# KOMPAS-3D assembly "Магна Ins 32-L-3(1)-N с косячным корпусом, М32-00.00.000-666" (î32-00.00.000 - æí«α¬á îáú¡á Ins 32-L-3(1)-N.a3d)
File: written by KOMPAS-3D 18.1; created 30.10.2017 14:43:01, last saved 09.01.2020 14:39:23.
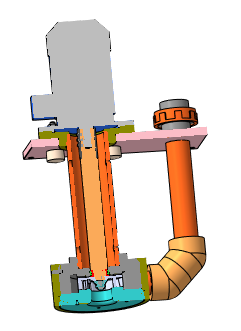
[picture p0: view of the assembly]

Document properties: Автор: Милов; Организация: Милов; Полное имя файла: D:\Magna\Магна Ins\Магна ins 32\Для Караби Магна 32\М32-00.00.000 - Сборка Магна Ins 32-L-3(1)-N.a3d

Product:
- Part/product: Магна Ins 32-L-3(1)-N с косячным корпусом  | designation М32-00.00.000-666
    Масса: 40.608
  - Component [detail]: Защитная втулка  | designation М11-00.00.003  | pos. 71  | Масса: 0.0186143; Раздел спецификации: Детали; Форматы листов документа: A4; source file: ..\..\Магна ins 11\Магна N\3Д\Магна INS 11\М11-00.00.003 - Защитная втулка.m3d, ..\..\Магна ins 11\Магна N\3Д\Магна INS 11\Чертежи\М11-00.00.003 - Защитная втулка.cdw
  - Component [detail]: Втулка / скольжения  | designation М11-00.00.002  | pos. 70  | Масса: 0.026501; Раздел спецификации: Детали; Форматы листов документа: A4
  - Component [detail]: Заглушка  | designation М32-00.00.007М32  | pos. 9  | Раздел спецификации: Детали; Форматы листов документа: A3; source file: ..\..\Магна ins 40\3Д\М40-00.00.007-01 - Заглушка.m3d, М32-00.00.007 - Заглушка.cdw
  - Component [detail]: Заглушка @2~32 FV PPR ф. "FV-Plast"  | qty 3  | pos. 19  | Материал: Полипропилен  ГОСТ 26996-86 (density 900 kg/m3); Масса: 0.0281994; Раздел спецификации: Прочие изделия
  - Component [detail]: Кольцо 120-125-30 EPDM / ГОСТ 9833-73  | pos. 18  | Раздел спецификации: Прочие изделия
  - Component [assembly]: Вал  | designation М32-00.10.000  | pos. 2  | Масса: 1.67698; Раздел спецификации: Сборочные единицы; Форматы листов документа: A3; Примечание: См. заказ
  - Component [assembly]: Корпус М32 с косячным корпусом М40  | designation М32-00.15.000-666  | pos. 1  | Масса: 9.75067; Раздел спецификации: Сборочные единицы; Форматы листов документа: A3; Примечание: См. заказ; source file: ..\М32-00.15.000 - Корпус М32.a3d
  - Component [detail]: Заглушка  | designation М32-00.00.007  | pos. 9  | Раздел спецификации: Детали; Форматы листов документа: A3
  - Component [detail]: Втулка  | designation М32-00.00.002  | pos. 7  | Раздел спецификации: Детали; Форматы листов документа: A4
  - Component [detail]: Защитная втулка  | designation М32-00.00.001  | pos. 6  | Раздел спецификации: Детали; Форматы листов документа: A4
  - Component [detail]: Косячная (удолить)  | designation М40-00.00.007-6666  | pos. 118  | Масса: 8.81523; Раздел спецификации: Детали; Форматы листов документа: 3xA3; Примечание: @100~)3xA3; source file: ..\..\Магна ins 40\3Д\М40-00.00.007-01 - Заглушка.m3d, ..\Магна ins 40\3Д\М40-00.00.007-06 - Заглушка.cdw
- Part/product: Сборка Магна Ins 32-L-3(1)-N  | designation М32-00.00.000
    Масса: 40.6372
    source file: М32-00.00.000 СБ - Магна Ins 32-L-3(1)-N.cdw
  - Component [standard]: Шайба C.14.21 ГОСТ 11371-78  | qty 7  | pos. 15
      Материал: Сталь 12Х18Н10Т ГОСТ 5632-72 (density 1000 kg/m3)
      Масса: 0.008377
      Раздел спецификации: Стандартные изделия
      Примечание: нерж.
      additional columns: Сталь 12Х18Н10Т ГОСТ 5632-72
      source file: C:\Program Files\ASCON\KOMPAS-3D v18\Libs\PartLib\DATA\VAULT\methods\kompas\3d\PLib_Washer_1_712.m3d
  - Component [detail]: Заглушка 32 FV PPR ф. "FV-Plast"  | qty 4  | pos. 19  | Материал: Полипропилен  ГОСТ 26996-86 (density 900 kg/m3); Масса: 0.0281994; Раздел спецификации: Прочие изделия; source file: Заглушка ф32 FV PPR ф. FV-Plast.m3d
  - Component [standard]: Шайба C.14.21 ГОСТ 11371-78  | qty 7  | pos. 15  | Материал: Сталь 12Х18Н10Т ГОСТ 5632-72 (density 1000 kg/m3); Масса: 0.008377; Раздел спецификации: Стандартные изделия; additional columns: Сталь 12Х18Н10Т ГОСТ 5632-72; source file: C:\Program Files\ASCON\KOMPAS-3D v18\Libs\PartLib\DATA\VAULT\methods\kompas\3d\PLib_Washer_1_712.m3d
  - Component [standard]: Шайба 14 30Х13 019 ГОСТ 6402-70  | qty 3  | pos. 120  | Материал: Сталь 30Х13 ГОСТ 5632-72 (density 1000 kg/m3); Масса: 0.00448; Раздел спецификации: Стандартные изделия; source file: C:\Program Files\ASCON\KOMPAS-3D v18\Libs\PartLib\DATA\VAULT\methods\kompas\3d\PLib_Washer_2_712.m3d
  - Component [standard]: Гайка М14-6H.21.12Х18Н10Т ГОСТ 5915-70  | qty 7  | pos. 13
      Материал: Сталь 12Х18Н10Т ГОСТ 5632-72 (density 1000 kg/m3)
      Масса: 0.02891
      Раздел спецификации: Стандартные изделия
      Примечание: нерж.
      additional columns: Сталь 12Х18Н10Т ГОСТ 5632-72
      source file: C:\Program Files\ASCON\KOMPAS-3D v18\Libs\PartLib\DATA\VAULT\methods\kompas\3d\PLib_Nut_OST92_900.m3d
  - Component [standard]: Болт М14-6gx80.21.12Х18Н10Т ГОСТ 7805-70  | qty 3  | pos. 119  | Материал: Сталь 12Х18Н10Т ГОСТ 5632-72 (density 1000 kg/m3); Масса: 0.1221; Раздел спецификации: Стандартные изделия; source file: C:\Program Files\ASCON\KOMPAS-3D v18\Libs\PartLib\DATA\VAULT\methods\kompas\3d\PLib_Bolt_1_900.m3d
  - Component [detail]: Рабочее колесо М32  | designation М32-00.00.003  | pos. 8  | Масса: 0.258528; Раздел спецификации: Детали; Форматы листов документа: A3; source file: М32-00.00.003 - Рабочее колесо М32.m3d
  - Component [detail]: Электродвигатель 90L2 380В 3кВт 3000об/мин 3081 / арт.: DRV090-L2-003-0-3030 DRIVE IEK  | pos. 21  | Масса: 19; Раздел спецификации: Прочие изделия; source file: Электродвигатель 90L2 380В 3кВт 3000об_мин 3081 DRIVE IEK.m3d
  - Component [standard]: Шайба 14 30Х13 019 ГОСТ 6402-70  | qty 3  | Материал: Сталь 30Х13 ГОСТ 5632-72 (density 1000 kg/m3); Масса: 0.00448; Раздел спецификации: Стандартные изделия; source file: C:\Program Files\ASCON\KOMPAS-3D v18\Libs\PartLib\DATA\VAULT\methods\kompas\3d\PLib_Washer_2_712.m3d
  - Component [standard]: Болт М14-6gx80.21.12Х18Н10Т ГОСТ 7805-70  | qty 3  | Материал: Сталь 12Х18Н10Т ГОСТ 5632-72 (density 1000 kg/m3); Масса: 0.1221; Раздел спецификации: Стандартные изделия; source file: C:\Program Files\ASCON\KOMPAS-3D v18\Libs\PartLib\DATA\VAULT\methods\kompas\3d\PLib_Bolt_1_900.m3d
  - Component [assembly]: Узел Корпус М32  | designation М32-00.15.000  | pos. 1  | Масса: 9.86598; Раздел спецификации: Сборочные единицы; Форматы листов документа: A3; Примечание: См. заказ; source file: М32-00.15.000 - Корпус М32.cdw, М32-00.15.000 - Узел Корпус М32.a3d
  - Component [assembly]: Узел Вал  | designation М32-00.10.000  | pos. 2  | Масса: 1.67698; Раздел спецификации: Сборочные единицы; Форматы листов документа: A3; Примечание: См. заказ; source file: C:\Users\User\Desktop\Вал _ М32-00.10.000.spw, М32-00.10.000 - Вал.cdw, М32-00.10.000 - Узел Вал.a3d
  - Component [detail]: Заглушка 32 FV PPR ф. "FV-Plast"  | qty 3  | pos. 19  | Материал: Полипропилен  ГОСТ 26996-86 (density 900 kg/m3); Масса: 0.0281994; Раздел спецификации: Прочие изделия; source file: ..\..\..\..\1 ПКИ 3D\Полипропиленовые фитинги, трубы\Заглушка ф32 FV PPR ф. FV-Plast.m3d
  - Component [detail]: Кольцо уплотнительное плоское 10-18-25 ЕPDM  | pos. 20  | Масса: 0.000562973; Раздел спецификации: Прочие изделия; source file: Кольцо уплотнительное плоское 10-18-25 ЕPDM.m3d
  - Component [detail]: Колпачок М10  | designation М40-00.00.009  | pos. 10  | Масса: 0.0397944; Раздел спецификации: Детали; Форматы листов документа: A3; source file: \\192.168.87.28\Konstructor_doc\Магна\Магна Ins\Магна ins 40\3Д\М40-00.00.009 - Колпачок М10.cdw, М40-00.00.009 - Колпачок М10.m3d
  - Component [detail]: Заглушка  | designation М32-00.00.007М32  | pos. 9  | Масса: 8.94851; Раздел спецификации: Детали; Форматы листов документа: A3; source file: ..\М32-00.00.007 - Заглушка.cdw, М40-00.00.007-01 - Заглушка.m3d
  - Component [detail]: Втулка скольжения  | designation М11-00.00.002  | pos. 70  | Масса: 0.026501; Раздел спецификации: Детали; Форматы листов документа: A4; source file: М11-00.00.002 - Втулка скольжения.m3d, Чертежи\М11-00.00.002 - Втулка скольжения.cdw
  - Component [detail]: Защитная втулка  | designation М11-00.00.003  | pos. 71  | Масса: 0.0186143; Раздел спецификации: Детали; Форматы листов документа: A4; source file: М11-00.00.003 - Защитная втулка.m3d, Чертежи\М11-00.00.003 - Защитная втулка.cdw

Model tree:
1. Массив по сетке:1  (with: Фаска:1)  (4 pattern instances)
     Шаг 1 = 150; Угол раствора = 90; Шаг 2 = 150
2. Массив по концентрической сетке:1  (with: Операция без истории:1)  (4 pattern instances)
     Шаг 2 = 360
3. ЛСК:1  (with: Плоскость XY, Плоскость ZX, Плоскость ZY, Ось X, Ось Y, Ось Z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)
     Ось X. X = -1; Ось Y. Y = -1; Ось Z. Z = 1; Координата X = 312; Координата Y = -162.5; Координата Z = 26.3725; Точка начала. Х = 312; Точка начала. Y = -162.5; Точка начала. Z = 26.3725
4. Сечение поверхностью:1
5. Сечение поверхностью:3
6. Сечение поверхностью:4  (with: Операция без истории:1, Операция выдавливания:1, Операция вращения:1, Отверстие:2, Вырезать элемент выдавливания:1, Отверстие:1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)  (labels: Операция выдавливания:1; Операция выдавливания:1; v184_h1)
     Расстояние = -0.5

Referenced files in D:\Magna\Магна Ins\Магна ins 32\Для Караби Магна 32\: М32-00.00.003 - Рабочее колесо М32.m3d, Электродвигатель 90L2 380В 3кВт 3000об_мин 3081 DRIVE IEK.m3d, М32-00.15.000 - Узел Корпус М32.a3d, М32-00.15.000 - Корпус М32.cdw, М32-00.10.000 - Узел Вал.a3d, М32-00.10.000 - Вал.cdw, Заглушка ф32 FV PPR ф. FV-Plast.m3d, Кольцо уплотнительное плоское 10-18-25 ЕPDM.m3d, М40-00.00.009 - Колпачок М10.m3d, М40-00.00.007-01 - Заглушка.m3d, М11-00.00.002 - Втулка скольжения.m3d, М11-00.00.003 - Защитная втулка.m3d
Referenced files in C:\Program Files\ASCON\KOMPAS-3D v18\Libs\PartLib\DATA\VAULT\methods\kompas\3d\: PLib_Washer_1_712.m3d, PLib_Nut_OST92_900.m3d, PLib_Bolt_1_900.m3d, PLib_Washer_2_712.m3d
Referenced files in C:\Users\User\Desktop\: Вал _ М32-00.10.000.spw
Referenced files in D:\1 ПКИ 3D\Полипропиленовые фитинги, трубы\: Заглушка ф32 FV PPR ф. FV-Plast.m3d
Referenced files in \\192.168.87.28\Konstructor_doc\Магна\Магна Ins\Магна ins 40\3Д\: М40-00.00.009 - Колпачок М10.cdw, М40-00.00.009 - Колпачок М10.m3d
Referenced files in D:\Magna\Магна Ins\Магна ins 32\Для Караби Магна 32\..\: М32-00.00.007 - Заглушка.cdw
Referenced files in D:\Magna\Магна Ins\Магна ins 32\Для Караби Магна 32\Чертежи\: М11-00.00.002 - Втулка скольжения.cdw, М11-00.00.003 - Защитная втулка.cdw
Referenced files in D:\Magna\Магна Ins\Магна ins 32\: М32-00.15.000 - Корпус М32.a3d, М32-00.00.007 - Заглушка.m3d, М32-00.00.001 - Защитная втулка.m3d, М32-00.00.002 -  Втулка.m3d, М32-00.10.000 - Вал.a3d
Referenced files in D:\Magna\Магна Ins\Магна ins 40\3Д\: М40-00.00.007-01 - Заглушка.m3d
Referenced files in C:\Program Files\ASCON\KOMPAS-3D V16\Libs\PartLib\DATA\VAULT\Methods\kompas\3d\: PLib_Washer_2_712.m3d, PLib_Bolt_1_900.m3d, PLib_Nut_OST92_900.m3d, PLib_Washer_1_712.m3d
Referenced files in D:\Magna\Магна Ins\Магна ins 32\Для Караби\: Заглушка ф32 FV PPR ф. FV-Plast.m3d
Referenced files in C:\Program Files\ASCON\KOMPAS-3D V16\Libs\PartLib\DATA\vault\Methods\Kompas\3D\: PLib_Washer_1_712.m3d
Referenced files in D:\Magna\Магна Ins\Магна ins 32\Архив\: М32-00.00.003 - Рабочее колесо М32.m3d
Referenced files in Z:\1 ПКИ 3D\РТИ\Кольца ГОСТ 9833-76\: Кольцо 120-125-30 EPDM ГОСТ 9833-73.m3d
Referenced files in D:\Magna\Магна Ins\Магна ins 40\3Д\Проработка\3Д\: Электродвигатель 90L2 380В 3кВт 3000об_мин 3081 DRIVE IEK.m3d
Referenced files in D:\1 ПКИ 3D\РТИ\Кольца уплотнительные  плоские\: Кольцо уплотнительное плоское 10-18-25 ЕPDM.m3d
Referenced files in D:\Magna\Магна Ins\Магна ins 11\Магна N\3Д\Магна INS 11\: М11-00.00.002 - Втулка скольжения.m3d, М11-00.00.003 - Защитная втулка.m3d
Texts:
  Крепежное изделие ГОСТ
  3D_Doc-graphic.lyt,1.000000-4294967295-182860482931
  Электродвигатель 90L2 380В 3кВт 3000об/мин 3081
  арт.: DRV090-L2-003-0-3030 DRIVE IEK
  Кольцо уплотнительное плоское
  Кольцо уплотнительное плоское / 10-18-25 ЕPDM
  @100~)3xA3
  Болт М14-6gx80.21.12Х18Н10Т ГОСТ 7805-70 (1)
  hole1
  hole2
  bcut1
  hcut1
  cut1
  Шайба 14 30Х13 019 ГОСТ 6402-70 (1)
  М11-00.00.002 Втулка скольжения
  М11-00.00.003 Защитная втулка

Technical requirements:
  Gost Type A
